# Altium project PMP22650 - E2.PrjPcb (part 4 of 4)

## Sheet PMP22650 CLLLC Primary Sensing.SchDoc
size 431 x 279 mm; Date: Not shown in title block; ApprovedBy: Not shown in title block; CheckedBy: Not shown in title block; Author: Not shown in title block; CompanyName: Not shown in title block; Engineer: Not shown in title block; Organization: Not shown in title block; Address1: Not shown in title block; Address2: Not shown in title block; Address3: Not shown in title block; Address4: Not shown in title block; DocumentNumber: 15; Revision: Use project parameter SCH_Rev; SheetNumber: 15; SheetTotal: 16; PageSetup: Record=PageOptions¦CenterHorizontal=True¦CenterVertical=True¦PrintScale=1.00¦XCorrection=1.00¦YCorrection=1.00¦PrintKind=0¦BorderSize=5000000¦LeftOffset=0¦BottomOffset=0¦Orientation=2¦PaperLength=1000¦PaperWidth=1000¦Scale=100¦PaperSource=15¦PrintQuality=600¦MediaType=1¦DitherType=10¦PaperKind=Letter¦PrintScaleMode=1
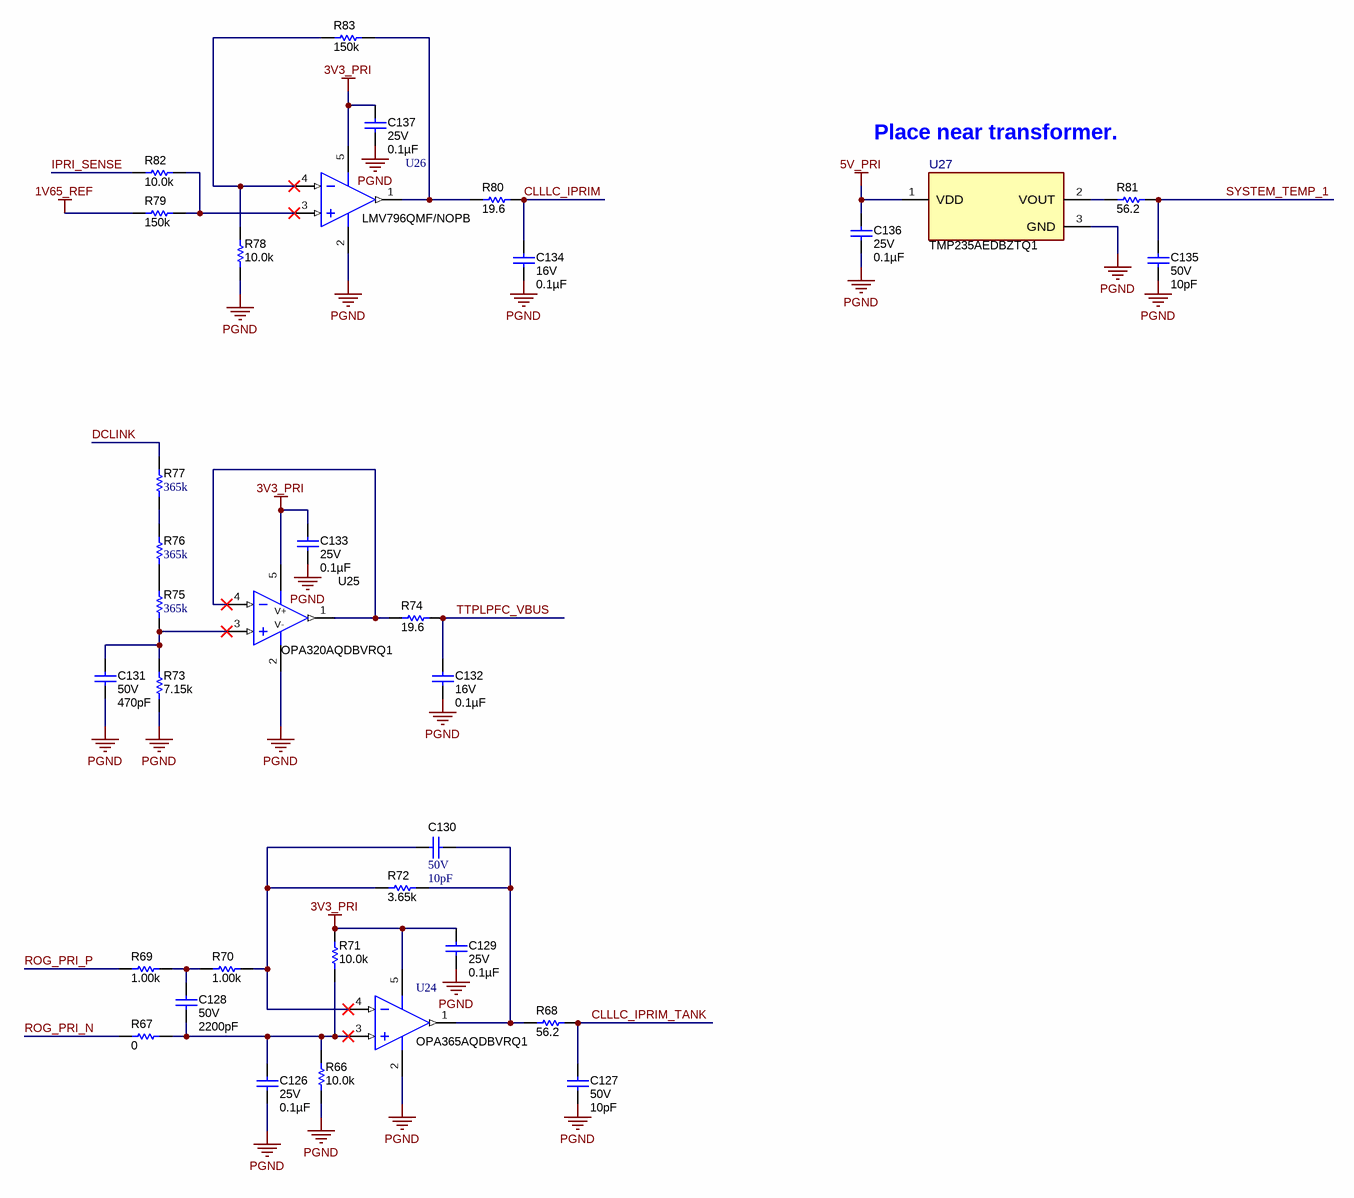
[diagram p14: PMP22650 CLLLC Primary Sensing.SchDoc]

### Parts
C126  VDC_V: 25V  ValueDisplayed: 0.1µF  [0402]  (hidden comment: CGA2B3X7R1E104K050BB)
C127  VDC_V: 50V  ValueDisplayed: 10pF  [0402]  (hidden comment: 04025U100CAT2A)
C128  VDC_V: 50V  ValueDisplayed: 2200pF  [0402]  (hidden comment: CGA2B2X7R1H222K050BA)
C129  VDC_V: 25V  ValueDisplayed: 0.1µF  [0402]  (hidden comment: CGA2B3X7R1E104K050BB)
C130  VDC_V: 50V  ValueDisplayed: 10pF  [0402]  (hidden comment: 04025U100CAT2A)
C131  VDC_V: 50V  ValueDisplayed: 470pF  [0402]  (hidden comment: GCM155R71H471KA37D)
C132  VDC_V: 16V  ValueDisplayed: 0.1µF  [0402]  (hidden comment: GCM155R71C104JA55D)
C133  VDC_V: 25V  ValueDisplayed: 0.1µF  [0402]  (hidden comment: CGA2B3X7R1E104K050BB)
C134  VDC_V: 16V  ValueDisplayed: 0.1µF  [0402]  (hidden comment: GCM155R71C104JA55D)
C135  VDC_V: 50V  ValueDisplayed: 10pF  [0402]  (hidden comment: 04025U100CAT2A)
C136  VDC_V: 25V  ValueDisplayed: 0.1µF  [0402]  (hidden comment: CGA2B3X7R1E104K050BB)
C137  VDC_V: 25V  ValueDisplayed: 0.1µF  [0402]  (hidden comment: CGA2B3X7R1E104K050BB)
R66  ValueDisplayed: 10.0k  [0402]  (hidden comment: ERJPA2F1002X)
R67  ValueDisplayed: 0  [0402]  (hidden comment: CRCW04020000Z0ED)
R68  ValueDisplayed: 56.2  [0402]  (hidden comment: CRCW040256R2FKED)
R69  ValueDisplayed: 1.00k  [0402]  (hidden comment: CRCW04021K00FKED)
R70  ValueDisplayed: 1.00k  [0402]  (hidden comment: CRCW04021K00FKED)
R71  ValueDisplayed: 10.0k  [0402]  (hidden comment: ERJPA2F1002X)
R72  ValueDisplayed: 3.65k  [0402]  (hidden comment: CRCW04023K65FKED)
R73  ValueDisplayed: 7.15k  [0603]  (hidden comment: CRCW06037K15FKEA)
R74  ValueDisplayed: 19.6  [0402]  (hidden comment: CRCW040219R6FKED)
R75  ValueDisplayed: 365k  [1206]  (hidden comment: CRCW1206365KFKEA)
R76  ValueDisplayed: 365k  [1206]  (hidden comment: CRCW1206365KFKEA)
R77  ValueDisplayed: 365k  [1206]  (hidden comment: CRCW1206365KFKEA)
R78  ValueDisplayed: 10.0k  [0402]  (hidden comment: ERJPA2F1002X)
R79  ValueDisplayed: 150k  [0402]  (hidden comment: CRCW0402150KFKED)
R80  ValueDisplayed: 19.6  [0402]  (hidden comment: CRCW040219R6FKED)
R81  ValueDisplayed: 56.2  [0402]  (hidden comment: CRCW040256R2FKED)
R82  ValueDisplayed: 10.0k  [0402]  (hidden comment: ERJPA2F1002X)
R83  ValueDisplayed: 150k  [0402]  (hidden comment: CRCW0402150KFKED)
U24  OPA365AQDBVRQ1  [DBV0005A_N]
U25  OPA320AQDBVRQ1  [DBV0005A_N]
U26  LMV796QMF/NOPB  [DBV0005A_N]
U27  TMP235AEDBZTQ1  [DBZ0003A-MFG]

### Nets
1V65_REF: R79.1
3V3_PRI: C129.1 C133.1 C137.1 R71.2 U24.5(V+) U25.5(V+) U26.5(V+)
5V_PRI: C136.1 U27.1(VDD)
DCLINK: R77.1
PGND: C126.2 C127.2 C129.2 C131.2 C132.2 C133.2 C134.2 C135.2 C136.2 C137.2 R66.1 R73.2 R78.1 U24.2(V-) U25.2(V-) U26.2(V-) U27.3(GND)
CLLLC_IPRIM: C134.1 R80.2
CLLLC_IPRIM_TANK: C127.1 R68.2
IPRI_SENSE: R82.1
ROG_PRI_N: R67.1
ROG_PRI_P: R69.1
SYSTEM_TEMP_1: C135.1 R81.2
TTPLPFC_VBUS: C132.1 R74.2
NetC126_1: C126.1 C128.1 R66.2 R67.2 R71.1 U24.3(IN+)
NetC128_2: C128.2 R69.2 R70.1
NetC130_1: C130.1 R68.1 R72.2 U24.1(VOUT)
NetC130_2: C130.2 R70.2 R72.1 U24.4(IN-)
NetC131_1: C131.1 R73.1 R75.2 U25.3(IN+)
NetR74_1: R74.1 U25.1(OUT) U25.4(IN-)
NetR75_1: R75.1 R76.2
NetR76_1: R76.1 R77.2
NetR78_2: R78.2 R83.1 U26.4(IN-)
NetR79_2: R79.2 R82.2 U26.3(IN+)
NetR80_1: R80.1 R83.2 U26.1(OUT)
NetR81_1: R81.1 U27.2(VOUT)

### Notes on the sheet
- Place near transformer.

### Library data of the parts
C126 C129 C133 C136 C137 = CMP-0080610-1: CAP, CERM, 0.1 µF, 25 V,+/- 10%, X7R, AEC-Q200 Grade 1, 0402; Manufacturer: TDK; TaMin_C: -55°C; Polarized: N; SizeAreaWB_mm2: 3; U/M: EA; Value: 0.1uF; TaMax_C: 125°C; SizeZ_mm: 0.6; SizeX_mm: 1; SizeY_mm: 0.5; AEC Qualified: Y; Cap_F: 100nF; AEC Category: Q200
C127 C130 C135 = CMP-0064911-2: CAP, CERM, 10 pF, 50 V,+/- 2.5%, C0G/NP0, AEC-Q200 Grade 1, 0402; Manufacturer: AVX; TaMin_C: -55°C; Polarized: N; SizeAreaWB_mm2: 3; Value1: Unknown; U/M: EA; Value: 10pF; TaMax_C: 125°C; SizeZ_mm: 0.6; SizeX_mm: 1; SizeY_mm: 0.5; AEC Qualified: Y; AEC Category: Q200
C128 = CMP-0006317-2: CAP, CERM, 2200 pF, 50 V, +/- 10%, X7R, AEC-Q200 Grade 1, 0402; Manufacturer: TDK; TaMin_C: -55°C; ESR_ohm: 1.07794; Polarized: N; SizeAreaWB_mm2: 3; Value1: 1.07794 ohm; U/M: EA; Value: 2200pF; TaMax_C: 125°C; SizeZ_mm: 0.6; SizeX_mm: 1; SizeY_mm: 0.5; AEC Qualified: Y; Cap_F: 2.2nF; IRMS_A: 264.071mA; AEC Category: Q200
C131 = CMP-0006360-2: CAP, CERM, 470 pF, 50 V, +/- 10%, X7R, AEC-Q200 Grade 1, 0402; Manufacturer: MuRata; TaMin_C: -55°C; Polarized: N; SizeAreaWB_mm2: 3; Value1: Unknown; U/M: EA; Value: 470pF; TaMax_C: 125°C; SizeZ_mm: 0.6; SizeX_mm: 1; SizeY_mm: 0.5; AEC Qualified: Y; AEC Category: Q200
C132 C134 = CMP-0080702-1: CAP, CERM, 0.1 µF, 16 V,+/- 5%, X7R, AEC-Q200 Grade 1, 0402; Manufacturer: MuRata; Cap_F: 100nF; SizeAreaWB_mm2: 3; SizeArea_mm2: 0.5; AEC Qualified: Y; AEC Category: Q200; Value: 0.1uF; TaMax_C: 125°C; SizeZ_mm: 0.6; AEC Grade: 1; Polarized: N; TaMin_C: -55°C; U/M: EA
R66 R71 R78 R82 = CMP-0078779-1: RES, 10.0 k, 1%, 0.2 W, AEC-Q200 Grade 0, 0402; Manufacturer: Panasonic; Value_Code: 10k0; SizeArea_mm2: 0.5; AEC Qualified: Y; AEC Category: Q200; Res_ohm: 10k; Value: 10.0k; SizeZ_mm: 0.6; EIA_Code: E96; TempCo: 100 ppm/C; AEC Grade: 0; Power_W: 200mW; VDC_V: 50V; Value2: 0.2W; SizeX_mm: 1
R67 = CMP-0026822-3: RES, 0, 5%, 0.063 W, AEC-Q200 Grade 0, 0402; Manufacturer: Vishay-Dale; Power_W: 63mW; TempCo: 200 ppm/C; Value_Code: 0000; Value: 0; EIA_Code: E24; SizeX_mm: 1; SizeY_mm: 0.5; SizeZ_mm: 0.6; Value2: 0.063W; AEC Qualified: Y; VDC_V: 50V; AEC Category: Q200
R68 R81 = CMP-0026454-2: RES, 56.2, 1%, 0.063 W, AEC-Q200 Grade 0, 0402; Manufacturer: Vishay-Dale; Power_W: 63mW; TempCo: 100 ppm/C; Value_Code: 56R2; Value: 56.2; EIA_Code: E96; SizeX_mm: 1; SizeY_mm: 0.5; SizeZ_mm: 0.6; Value2: 0.063W; AEC Qualified: Y; VDC_V: 50V; AEC Category: Q200; AEC Grade: 0
R69 R70 = CMP-0026071-3: RES, 1.00 k, 1%, 0.063 W, AEC-Q200 Grade 0, 0402; Manufacturer: Vishay-Dale; Power_W: 63mW; TempCo: 100 ppm/C; Value_Code: 1k00; Value: 1.00k; EIA_Code: E96; Res_ohm: 1k; SizeX_mm: 1; SizeY_mm: 0.5; SizeZ_mm: 0.6; Value2: 0.063W; AEC Qualified: Y; VDC_V: 50V; AEC Category: Q200; AEC Grade: 0
R72 = CMP-0026337-2: RES, 3.65 k, 1%, 0.063 W, AEC-Q200 Grade 0, 0402; Manufacturer: Vishay-Dale; Power_W: 63mW; TempCo: 100 ppm/C; Value_Code: 3k65; Value: 3.65k; EIA_Code: E96; SizeX_mm: 1; SizeY_mm: 0.5; SizeZ_mm: 0.6; Value2: 0.063W; AEC Qualified: Y; VDC_V: 50V; AEC Category: Q200; AEC Grade: 0
R73 = CMP-0022599-4: RES, 7.15 k, 1%, 0.1 W, AEC-Q200 Grade 0, 0603; Manufacturer: Vishay-Dale; Power_W: 100mW; TempCo: 100 ppm/C; Value_Code: 7k15; Value: 7.15k; EIA_Code: E96; SizeX_mm: 1.6; SizeY_mm: 0.8; SizeZ_mm: 1; Value2: 0.1W; SizeArea_mm2: 1.28; AEC Qualified: Y; VDC_V: 75V; AEC Category: Q200; AEC Grade: 0
R74 R80 = CMP-0026070-3: RES, 19.6, 1%, 0.063 W, AEC-Q200 Grade 0, 0402; Manufacturer: Vishay-Dale; Power_W: 63mW; TempCo: 100 ppm/C; Value_Code: 19R6; Value: 19.6; EIA_Code: E96; SizeX_mm: 1; SizeY_mm: 0.5; SizeZ_mm: 0.6; Value2: 0.063W; AEC Qualified: Y; VDC_V: 50V; AEC Category: Q200; AEC Grade: 0
R75-R77 = CMP-0016927-3: RES, 365 k, 1%, 0.25 W, AEC-Q200 Grade 0, 1206; Manufacturer: Vishay-Dale; Power_W: 250mW; TempCo: 100 ppm/C; Value: 365k; EIA_Code: E96; SizeX_mm: 3.2; SizeY_mm: 1.6; SizeZ_mm: 1.35; Value2: 0.25W; SizeArea_mm2: 5.12; AEC Qualified: Y; VDC_V: 200V; AEC Category: Q200; AEC Grade: 0
R79 R83 = CMP-0026021-3: RES, 150 k, 1%, 0.063 W, AEC-Q200 Grade 0, 0402; Manufacturer: Vishay-Dale; Power_W: 63mW; TempCo: 100 ppm/C; Value: 150k; EIA_Code: E96; SizeX_mm: 1; SizeY_mm: 0.5; SizeZ_mm: 0.6; Value2: 0.063W; AEC Qualified: Y; VDC_V: 50V; AEC Category: Q200; AEC Grade: 0
U24 = CMP-0041005-2: Automotive Catalog, 50 MHz, Low-Noise, Single-Supply Rail-to-Rail Operational Amplifier, 2.2 to 5.5 V, -40 to 125 degC, 5-pin SOT23 (DBV5), Green (RoHS & no Sb/Br); Manufacturer: Texas Instruments; Sub Family: High Speed Amplifier (>=50MHz), Low Input Bias Current Amp (<=10pA), Low Offset Voltage Amplifier (<=500uV), Low Supply Voltage Amplifier (<=2.7V); Total Supply Voltage(Min)(+5V is 5, +/-5V is 10): 2.2; Slew Rate(Typ)(V/us): 25; Vio (25C)(Max)(mV): 0.2; Total Supply Voltage(Max)(+5V is 5, +/-5V is 10): 5.5; IIB(Max)(pA): 10; Offset Drift(Typ)(uV/C): 1; Iq per channel(Max)(mA): 5; CMRR(Min)(dB): 100
U25 = CMP-0077859-1: Automotive Qualified Precision, Zero-Crossover, 20MHz, 0.9pA Ib, RRIO, CMOS Operational Amplifier, DBV0005A (SOT-23-5); Alternate PartNumber: OPA320AQDBVTQ1; Alternate Manufacturer: Texas Instruments; SizeAreaWB_mm2: 14.82; SizeZ_mm: 1.45; SizeX_mm: 2.8; SizeY_mm: 2.9; SizeArea_mm2: 8.12; CompType: IC; AEC Qualified: Y; AEC Category: Q200
U26 = CMP-0068826-2: 17 MHz, Low Noise, CMOS Input, 1.8V Operational Amplifiers, DBV0005A (SOT-23-5); Manufacturer: Texas Instruments; CompType: IC; AEC Category: Q200; AEC Qualified: Y; Rating: Automotive; SizeAreaWB_mm2: 14.82; SizeArea_mm2: 8.12; SizeX_mm: 2.8; SizeY_mm: 2.9; SizeZ_mm: 1.45
U27 = CMP-0090472-1: Temperature Sensor Analog, Local -40°C ~ 150°C 10mV/°C SOT-23-3; Manufacturer: Texas Instruments; TJmax_C: +150°C; Min Supply Voltage: 2.3V; SizeZ_mm: 1.12mm; Max Supply Voltage: 5.5V; Interface: Other; AEC Qualified: Yes; Output Voltage: 500mV; AEC Grade: Grade 0; Standoff Height: 0.01mm; Sensor Output: Analog Voltage; Operating Supply Current: 9uA

## Sheet PMP22650 CLLLC Secondary Sensing.SchDoc
size 431 x 279 mm; Date: Not shown in title block; ApprovedBy: Not shown in title block; CheckedBy: Not shown in title block; Author: Not shown in title block; CompanyName: Not shown in title block; Engineer: Not shown in title block; Organization: Not shown in title block; Address1: Not shown in title block; Address2: Not shown in title block; Address3: Not shown in title block; Address4: Not shown in title block; DocumentNumber: 16; Revision: Use project parameter SCH_Rev; SheetNumber: 16; SheetTotal: 16; PageSetup: Record=PageOptions¦CenterHorizontal=True¦CenterVertical=True¦PrintScale=1.00¦XCorrection=1.00¦YCorrection=1.00¦PrintKind=0¦BorderSize=5000000¦LeftOffset=0¦BottomOffset=0¦Orientation=2¦PaperLength=1000¦PaperWidth=1000¦Scale=100¦PaperSource=15¦PrintQuality=600¦MediaType=1¦DitherType=10¦PaperKind=Letter¦PrintScaleMode=1
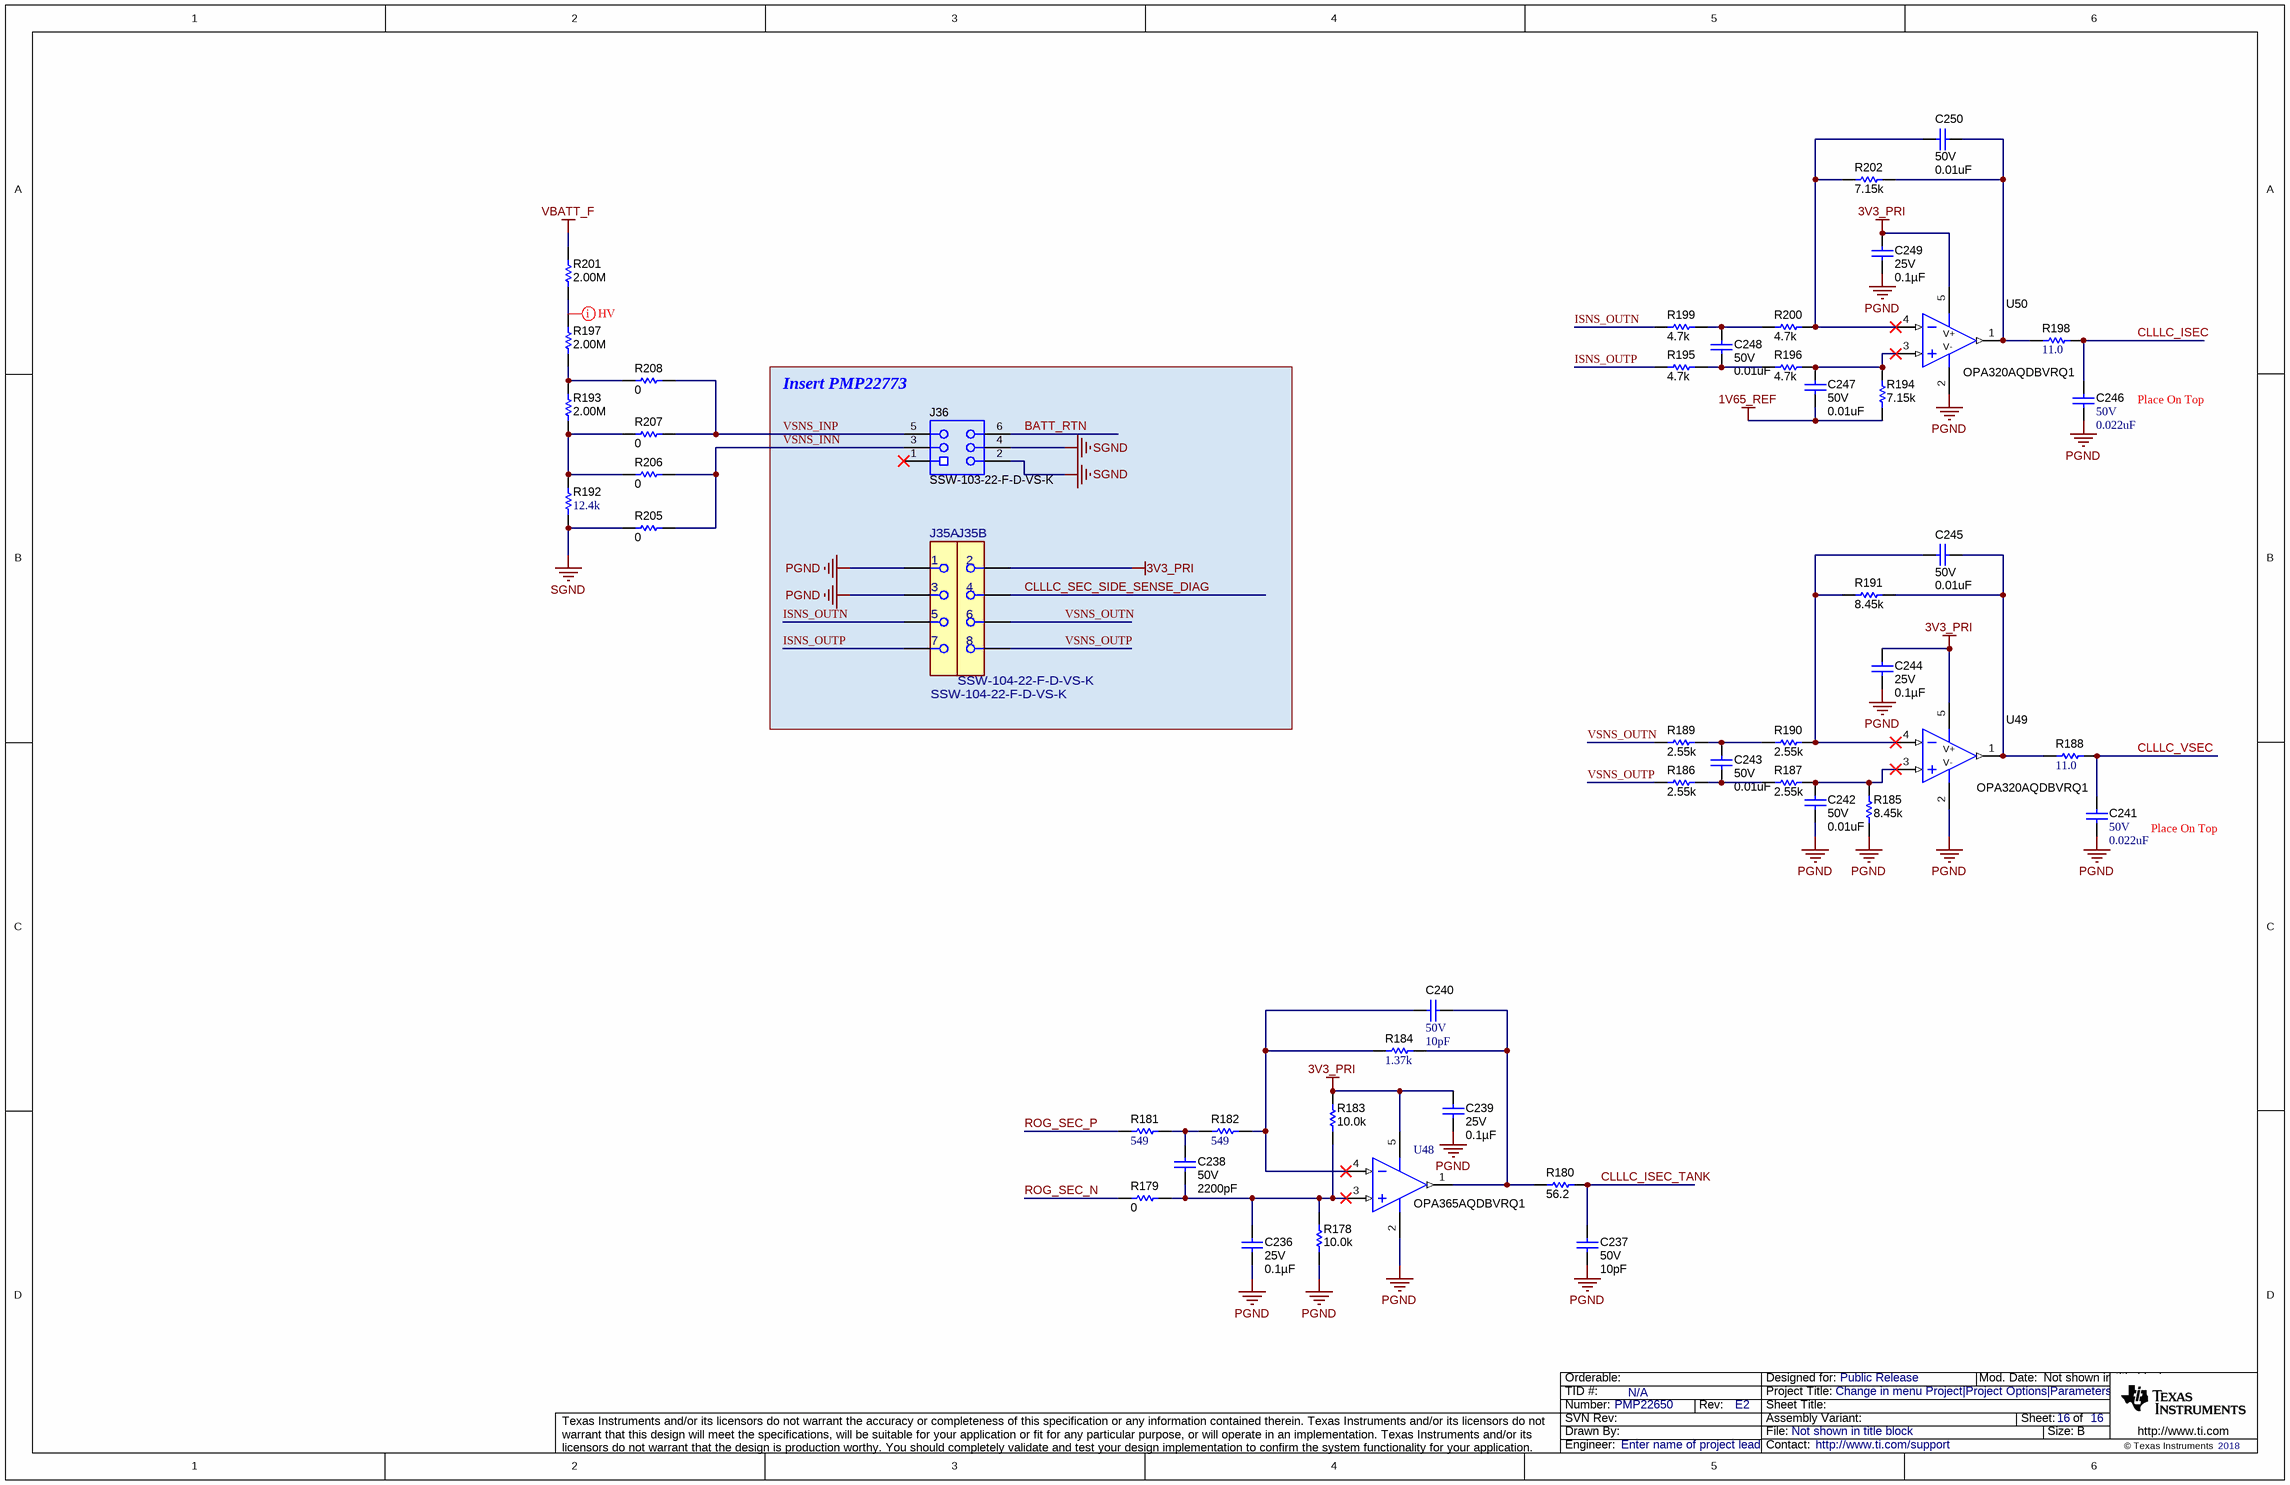
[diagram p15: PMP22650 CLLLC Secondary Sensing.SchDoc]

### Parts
C236  VDC_V: 25V  ValueDisplayed: 0.1µF  [0402]  (hidden comment: CGA2B3X7R1E104K050BB)
C237  VDC_V: 50V  ValueDisplayed: 10pF  [0402]  (hidden comment: 04025U100CAT2A)
C238  VDC_V: 50V  ValueDisplayed: 2200pF  [0402]  (hidden comment: CGA2B2X7R1H222K050BA)
C239  VDC_V: 25V  ValueDisplayed: 0.1µF  [0402]  (hidden comment: CGA2B3X7R1E104K050BB)
C240  VDC_V: 50V  ValueDisplayed: 10pF  [0402]  (hidden comment: 04025U100CAT2A)
C241  VDC_V: 50V  ValueDisplayed: 0.022uF  [0402]  (hidden comment: CGA2B3X7R1H223K050BB)
C242  VDC_V: 50V  ValueDisplayed: 0.01uF  [0402]  (hidden comment: CGA2B3X7R1H103K050BB)
C243  VDC_V: 50V  ValueDisplayed: 0.01uF  [0402]  (hidden comment: CGA2B3X7R1H103K050BB)
C244  VDC_V: 25V  ValueDisplayed: 0.1µF  [0402]  (hidden comment: CGA2B3X7R1E104K050BB)
C245  VDC_V: 50V  ValueDisplayed: 0.01uF  [0402]  (hidden comment: CGA2B3X7R1H103K050BB)
C246  VDC_V: 50V  ValueDisplayed: 0.022uF  [0402]  (hidden comment: CGA2B3X7R1H223K050BB)
C247  VDC_V: 50V  ValueDisplayed: 0.01uF  [0402]  (hidden comment: CGA2B3X7R1H103K050BB)
C248  VDC_V: 50V  ValueDisplayed: 0.01uF  [0402]  (hidden comment: CGA2B3X7R1H103K050BB)
C249  VDC_V: 25V  ValueDisplayed: 0.1µF  [0402]  (hidden comment: CGA2B3X7R1E104K050BB)
C250  VDC_V: 50V  ValueDisplayed: 0.01uF  [0402]  (hidden comment: CGA2B3X7R1H103K050BB)
J35  SSW-104-22-F-D-VS-K  [FP-SSW-104-22-F-D-VS-K_HDR8-MFG]  (parts A,B of 2)
J36  SSW-103-22-F-D-VS-K  [SAMTEC_SSW-103-22-F-D-VS-K]
R178  ValueDisplayed: 10.0k  [0402]  (hidden comment: ERJPA2F1002X)
R179  ValueDisplayed: 0  [0402]  (hidden comment: CRCW04020000Z0ED)
R180  ValueDisplayed: 56.2  [0402]  (hidden comment: CRCW040256R2FKED)
R181  ValueDisplayed: 549  [0402]  (hidden comment: CRCW0402549RFKED)
R182  ValueDisplayed: 549  [0402]  (hidden comment: CRCW0402549RFKED)
R183  ValueDisplayed: 10.0k  [0402]  (hidden comment: ERJPA2F1002X)
R184  ValueDisplayed: 1.37k  [0402]  (hidden comment: CRCW04021K37FKED)
R185  ValueDisplayed: 8.45k  [0603]  (hidden comment: CRCW06038K45FKEA)
R186  ValueDisplayed: 2.55k  [0402]  (hidden comment: CRCW04022K55FKED)
R187  ValueDisplayed: 2.55k  [0402]  (hidden comment: CRCW04022K55FKED)
R188  ValueDisplayed: 11.0  [0402]  (hidden comment: CRCW040211R0FKED)
R189  ValueDisplayed: 2.55k  [0402]  (hidden comment: CRCW04022K55FKED)
R190  ValueDisplayed: 2.55k  [0402]  (hidden comment: CRCW04022K55FKED)
R191  ValueDisplayed: 8.45k  [0603]  (hidden comment: CRCW06038K45FKEA)
R192  ValueDisplayed: 12.4k  [1206]  (hidden comment: ERJ-8ENF1242V)
R193  ValueDisplayed: 2.00M  [1206]  (hidden comment: CRCW12062M00FKEA)
R194  ValueDisplayed: 7.15k  [0402]  (hidden comment: CRCW04027K15FKED)
R195  ValueDisplayed: 4.7k  [0402]  (hidden comment: CRCW04024K70JNED)
R196  ValueDisplayed: 4.7k  [0402]  (hidden comment: CRCW04024K70JNED)
R197  ValueDisplayed: 2.00M  [1206]  (hidden comment: CRCW12062M00FKEA)
R198  ValueDisplayed: 11.0  [0402]  (hidden comment: CRCW040211R0FKED)
R199  ValueDisplayed: 4.7k  [0402]  (hidden comment: CRCW04024K70JNED)
R200  ValueDisplayed: 4.7k  [0402]  (hidden comment: CRCW04024K70JNED)
R201  ValueDisplayed: 2.00M  [1206]  (hidden comment: CRCW12062M00FKEA)
R202  ValueDisplayed: 7.15k  [0402]  (hidden comment: CRCW04027K15FKED)
R205  ValueDisplayed: 0  [0402]  (hidden comment: CRCW04020000Z0ED)
R206  ValueDisplayed: 0  [0402]  (hidden comment: CRCW04020000Z0ED)
R207  ValueDisplayed: 0  [0402]  (hidden comment: CRCW04020000Z0ED)
R208  ValueDisplayed: 0  [0402]  (hidden comment: CRCW04020000Z0ED)
U48  OPA365AQDBVRQ1  [DBV0005A_N]
U49  OPA320AQDBVRQ1  [DBV0005A_N]
U50  OPA320AQDBVRQ1  [DBV0005A_N]

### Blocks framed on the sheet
Insert PMP22773: J35 J36

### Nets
1V65_REF: C247.1 R194.1
3V3_PRI: C239.1 C244.1 C249.1 J35.2 R183.2 U48.5(V+) U49.5(V+) U50.5(V+)
PGND: C236.2 C237.2 C239.2 C241.2 C242.1 C244.2 C246.2 C249.2 J35.1 J35.3 R178.1 R185.1 U48.2(V-) U49.2(V-) U50.2(V-)
SGND: J36.2 J36.4 R192.2 R205.1
VBATT_F: R201.2
BATT_RTN: J36.6
CLLLC_ISEC: C246.1 R198.2
CLLLC_ISEC_TANK: C237.1 R180.2
CLLLC_SEC_SIDE_SENSE_DIAG: J35.4
CLLLC_VSEC: C241.1 R188.2
ISNS_OUTN: J35.5 R199.1
ISNS_OUTP: J35.7 R195.1
ROG_SEC_N: R179.1
ROG_SEC_P: R181.1
VSNS_INN: J36.3 R205.2 R206.2
VSNS_INP: J36.5 R207.2 R208.2
VSNS_OUTN: J35.6 R189.1
VSNS_OUTP: J35.8 R186.1
NetC236_1: C236.1 C238.1 R178.2 R179.2 R183.1 U48.3(IN+)
NetC238_2: C238.2 R181.2 R182.1
NetC240_1: C240.1 R180.1 R184.2 U48.1(VOUT)
NetC240_2: C240.2 R182.2 R184.1 U48.4(IN-)
NetC242_2: C242.2 R185.2 R187.2 U49.3(IN+)
NetC243_1: C243.1 R186.2 R187.1
NetC243_2: C243.2 R189.2 R190.1
NetC245_1: C245.1 R188.1 R191.2 U49.1(OUT)
NetC245_2: C245.2 R190.2 R191.1 U49.4(IN-)
NetC247_2: C247.2 R194.2 R196.2 U50.3(IN+)
NetC248_1: C248.1 R195.2 R196.1
NetC248_2: C248.2 R199.2 R200.1
NetC250_1: C250.1 R198.1 R202.2 U50.1(OUT)
NetC250_2: C250.2 R200.2 R202.1 U50.4(IN-)
NetR192_1: R192.1 R193.1 R206.1 R207.1
NetR193_2: R193.2 R197.1 R208.1
NetR197_2: R197.2 R201.1

Not connected (* = marked no-connect by the designer): J36 1*

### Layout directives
mark named HV: NetR197_2

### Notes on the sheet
- Place On Top

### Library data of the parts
C236 C239 C244 C249 = CMP-0080610-1: as C126 on sheet PMP22650 CLLLC Primary Sensing
C237 C240 = CMP-0064911-2: as C127 on sheet PMP22650 CLLLC Primary Sensing
C238 = CMP-0006317-2: as C128 on sheet PMP22650 CLLLC Primary Sensing
C241 C246 = CMP-0006328-2: CAP, CERM, 0.022 uF, 50 V, +/- 10%, X7R, AEC-Q200 Grade 1, 0402; Manufacturer: TDK; TaMin_C: -55°C; Polarized: N; SizeAreaWB_mm2: 3; Value1: 0.141987 ohm; U/M: EA; TaMax_C: 125°C; SizeZ_mm: 0.6; SizeX_mm: 1; SizeY_mm: 0.5; AEC Qualified: Y; Cap_F: 22nF; AEC Category: Q200; ESR_ohm: 0.142; IRMS_A: 451.393mA
C242 C243 C245 C247 C248 C250 = CMP-0006324-2: CAP, CERM, 0.01 uF, 50 V, +/- 10%, X7R, AEC-Q200 Grade 1, 0402; Manufacturer: TDK; TaMin_C: -55°C; ESR_ohm: 0.333065; Polarized: N; SizeAreaWB_mm2: 3; Value1: 0.333065 ohm; U/M: EA; Value: 0.01uF; TaMax_C: 125°C; SizeZ_mm: 0.6; SizeX_mm: 1; SizeY_mm: 0.5; AEC Qualified: Y; Cap_F: 10nF; IRMS_A: 323.373mA; AEC Category: Q200
J35 = CMP-0090885-1: 8 Position Receptacle Connector  Surface Mount; Manufacturer: Samtec; Standoff Height: 0.97mm; Is Female: yes; Row_Count: 2; ContactFinish: Gold,Nickel; Voltage_V: 655V; AEC Qualified: No; Current_A: 4.7A; Conn Gender: Female; SizeZ_mm: 10.21mm; Conn Orientation: Vertical; DUT-Pitch_mm: 2.54mm
J36 = CMP-0055666-1: Receptacle, 2.54mm, 3x2, Tin, SMT; Manufacturer: Samtec; CNHeader: FALSE; Current_A: 5.7A; Gender: Female; CompType: Socket Strip; Row_Count: 2; RowSpacing_mm: 2.54; ContactFinish: Gold; CT: TRUE; Cert_UL: Y
R178 R183 = CMP-0078779-1: as R66 on sheet PMP22650 CLLLC Primary Sensing
R179 R205-R208 = CMP-0026822-3: as R67 on sheet PMP22650 CLLLC Primary Sensing
R180 = CMP-0026454-2: as R68 on sheet PMP22650 CLLLC Primary Sensing
R181 R182 = CMP-0026448-2: RES, 549, 1%, 0.063 W, AEC-Q200 Grade 0, 0402; Manufacturer: Vishay-Dale; Power_W: 63mW; TempCo: 100 ppm/C; Value_Code: 549R; Value: 549; EIA_Code: E96; SizeX_mm: 1; SizeY_mm: 0.5; SizeZ_mm: 0.6; Value2: 0.063W; AEC Qualified: Y; VDC_V: 50V; AEC Category: Q200; AEC Grade: 0
R184 = CMP-0026084-3: RES, 1.37 k, 1%, 0.063 W, AEC-Q200 Grade 0, 0402; Manufacturer: Vishay-Dale; Power_W: 63mW; TempCo: 100 ppm/C; Value_Code: 1k37; Value: 1.37k; EIA_Code: E96; SizeX_mm: 1; SizeY_mm: 0.5; SizeZ_mm: 0.6; Value2: 0.063W; AEC Qualified: Y; VDC_V: 50V; AEC Category: Q200; AEC Grade: 0
R185 R191 = CMP-0022636-4: RES, 8.45 k, 1%, 0.1 W, AEC-Q200 Grade 0, 0603; Manufacturer: Vishay-Dale; Power_W: 100mW; TempCo: 100 ppm/C; Value_Code: 8k45; Value: 8.45k; EIA_Code: E96; SizeX_mm: 1.6; SizeY_mm: 0.8; SizeZ_mm: 1; Value2: 0.1W; SizeArea_mm2: 1.28; AEC Qualified: Y; VDC_V: 75V; AEC Category: Q200; AEC Grade: 0
R186 R187 R189 R190 = CMP-0026238-2: RES, 2.55 k, 1%, 0.063 W, AEC-Q200 Grade 0, 0402; Manufacturer: Vishay-Dale; Power_W: 63mW; TempCo: 100 ppm/C; Value_Code: 2k55; Value: 2.55k; EIA_Code: E96; SizeX_mm: 1; SizeY_mm: 0.5; SizeZ_mm: 0.6; Value2: 0.063W; AEC Qualified: Y; VDC_V: 50V; AEC Category: Q200; AEC Grade: 0
R188 R198 = CMP-0025979-3: RES, 11.0, 1%, 0.063 W, AEC-Q200 Grade 0, 0402; Manufacturer: Vishay-Dale; Power_W: 63mW; TempCo: 100 ppm/C; Value_Code: 11R0; Value: 11.0; EIA_Code: E96; Res_ohm: 11; SizeX_mm: 1; SizeY_mm: 0.5; SizeZ_mm: 0.6; Value2: 0.063W; AEC Qualified: Y; VDC_V: 50V; AEC Category: Q200; AEC Grade: 0
R192 = CMP-0017331-3: RES, 12.4 k, 1%, 0.25 W, AEC-Q200 Grade 0, 1206; Manufacturer: Panasonic; Power_W: 250mW; TempCo: 100 ppm/C; Value_Code: 12k4; Value: 12.4k; EIA_Code: E96; SizeX_mm: 3.2; SizeY_mm: 1.6; SizeZ_mm: 1.35; Value2: 0.25W; SizeArea_mm2: 5.12; AEC Qualified: Y; VDC_V: 200V; AEC Category: Q200; AEC Grade: 0; SizeAreaWB_mm2: 10.92
R193 R197 R201 = CMP-0016861-3: RES, 2.00 M, 1%, 0.25 W, AEC-Q200 Grade 0, 1206; Manufacturer: Vishay-Dale; Power_W: 250mW; TempCo: 100 ppm/C; Value_Code: 2M00; Value: 2.00Meg; EIA_Code: E96; Res_ohm: 2M; SizeX_mm: 3.2; SizeY_mm: 1.6; SizeZ_mm: 1.35; Value2: 0.25W; SizeArea_mm2: 5.12; AEC Qualified: Y; VDC_V: 200V; AEC Category: Q200; AEC Grade: 0
R194 R202 = CMP-0026553-2: RES, 7.15 k, 1%, 0.063 W, AEC-Q200 Grade 0, 0402; Manufacturer: Vishay-Dale; Power_W: 63mW; TempCo: 100 ppm/C; Value_Code: 7k15; Value: 7.15k; EIA_Code: E96; SizeX_mm: 1; SizeY_mm: 0.5; SizeZ_mm: 0.6; Value2: 0.063W; AEC Qualified: Y; VDC_V: 50V; AEC Category: Q200; AEC Grade: 0
R195 R196 R199 R200 = CMP-0026938-5: RES, 4.7 k, 5%, 0.063 W, AEC-Q200 Grade 0, 0402; Manufacturer: Vishay-Dale; Power_W: 63mW; TempCo: 200 ppm/C; Value_Code: 4k70; Value: 4.7k; EIA_Code: E24; SizeX_mm: 1; SizeY_mm: 0.5; SizeZ_mm: 0.6; Value2: 0.063W; AEC Qualified: Y; VDC_V: 50V; AEC Category: Q200; AEC Grade: 0
U48 = CMP-0041005-2: as U24 on sheet PMP22650 CLLLC Primary Sensing
U49 U50 = CMP-0077859-1: as U25 on sheet PMP22650 CLLLC Primary Sensing

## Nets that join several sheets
1V65_REF: PMP22650 PFC Power Stage (5 pins), PMP22650 Control (J26.26), PMP22650 Bias Power and Monitors (C23.1 R7.2), PMP22650 CLLLC Primary Sensing (R79.1), PMP22650 CLLLC Secondary Sensing (C247.1 R194.1)
3V3_PRI: PMP22650 PFC Power Stage (14 pins), PMP22650 PFC GaN PH1 (6 pins), PMP22650 PFC GaN PH2 (6 pins), PMP22650 PFC LF FET Gate Driver (C198.1 U42.3 U42.8), PMP22650 Control (16 pins), PMP22650 Bias Power and Monitors (14 pins), PMP22650 CLLLC GaN Phase A (6 pins), PMP22650 CLLLC GaN Phase B (6 pins), PMP22650 CLLLC GaN Phase C (6 pins), PMP22650 CLLLC GaN Phase D (6 pins), PMP22650 CLLLC Primary Sensing (7 pins), PMP22650 CLLLC Secondary Sensing (8 pins)
5V_PRI: PMP22650 PFC GaN PH1 (J27.5), PMP22650 PFC GaN PH2 (J29.5), PMP22650 PFC LF FET Gate Driver (J31.5), PMP22650 Control (6 pins), PMP22650 Bias Power and Monitors (16 pins), PMP22650 CLLLC Power Stage (J12.5), PMP22650 CLLLC GaN Phase A (J16.5), PMP22650 CLLLC GaN Phase B (J18.5), PMP22650 CLLLC GaN Phase C (J20.5), PMP22650 CLLLC GaN Phase D (J22.5), PMP22650 CLLLC Primary Sensing (C136.1 U27.1)
12V_PRI: PMP22650 PFC Power Stage (C214.1 R157.2 R158.2), PMP22650 Bias Power and Monitors (6 pins), PMP22650 CLLLC Power Stage (J12.1 J12.2)
12V_SW: PMP22650 Active EMI (J34.1), PMP22650 PFC GaN PH1 (J27.1 J27.3), PMP22650 PFC GaN PH2 (J29.1 J29.3), PMP22650 PFC LF FET Gate Driver (J31.1 J31.3), PMP22650 Bias Power and Monitors (Q4.1 Q4.2 Q4.5 Q4.6), PMP22650 CLLLC GaN Phase A (J16.1 J16.3), PMP22650 CLLLC GaN Phase B (J18.1 J18.3), PMP22650 CLLLC GaN Phase C (J20.1 J20.3), PMP22650 CLLLC GaN Phase D (J22.1 J22.3)
DCLINK: PMP22650 PFC Power Stage (13 pins), PMP22650 PFC GaN PH1 (24 pins), PMP22650 PFC GaN PH2 (24 pins), PMP22650 Control (R96.1), PMP22650 CLLLC Power Stage (10 pins), PMP22650 CLLLC GaN Phase A (24 pins), PMP22650 CLLLC GaN Phase B (24 pins), PMP22650 CLLLC Primary Sensing (R77.1)
EARTH: PMP22650 Active EMI (C234.1 C235.2), PMP22650 PFC Power Stage (9 pins)
PGND: PMP22650 Active EMI (6 pins), PMP22650 PFC Power Stage (38 pins), PMP22650 PFC GaN PH1 (13 pins), PMP22650 PFC GaN PH2 (13 pins), PMP22650 PFC LF FET Gate Driver (9 pins), PMP22650 Control (35 pins), PMP22650 Bias Power and Monitors (39 pins), PMP22650 CLLLC Power Stage (14 pins), PMP22650 CLLLC GaN Phase A (54 pins), PMP22650 CLLLC GaN Phase B (54 pins), PMP22650 CLLLC GaN Phase C (13 pins), PMP22650 CLLLC GaN Phase D (13 pins), PMP22650 CLLLC Primary Sensing (17 pins), PMP22650 CLLLC Secondary Sensing (15 pins)
SGND: PMP22650 CLLLC Power Stage (12 pins), PMP22650 CLLLC GaN Phase C (41 pins), PMP22650 CLLLC GaN Phase D (41 pins), PMP22650 CLLLC Secondary Sensing (J36.2 J36.4 R192.2 R205.1)
VBATT_F: PMP22650 CLLLC Power Stage (6 pins), PMP22650 CLLLC GaN Phase C (24 pins), PMP22650 CLLLC GaN Phase D (24 pins), PMP22650 CLLLC Secondary Sensing (R201.2)
VDD: PMP22650 Control (J26.118), PMP22650 Bias Power and Monitors (U4.10)
VDDIO: PMP22650 Control (J26.119), PMP22650 Bias Power and Monitors (U5.1)
AC_N: PMP22650 PFC Power Stage (10 pins), PMP22650 PFC LF FET Gate Driver (7 pins)
ACTIVE_EMI_INJ_PD_LEVEL: PMP22650 Active EMI (J34.8), PMP22650 Control (J26.9)
ACTIVE_EMI_INJ_PD_PULSE: PMP22650 Active EMI (J34.7), PMP22650 Control (J26.69)
ACTIVE_EMI_INJ_PU_PULSE: PMP22650 Active EMI (J34.6), PMP22650 Control (J26.67)
ACTIVE_EMI_RESET: PMP22650 Active EMI (R176.2), PMP22650 Control (J26.87)
ACTIVE_EMI_SENSE: PMP22650 Active EMI (C233.1 Q10.3 R177.1), PMP22650 Control (J26.36)
BATT_RTN: PMP22650 CLLLC Power Stage (9 pins), PMP22650 CLLLC Secondary Sensing (J36.6)
CLLLC_GAN_OC_PRIM_LEG1_H: PMP22650 Control (J26.99), PMP22650 CLLLC GaN Phase A (U10.13)
CLLLC_GAN_OC_PRIM_LEG1_L: PMP22650 Control (J26.107), PMP22650 CLLLC GaN Phase A (U8.13)
CLLLC_GAN_OC_PRIM_LEG2_H: PMP22650 Control (J26.109), PMP22650 CLLLC GaN Phase B (U14.13)
CLLLC_GAN_OC_PRIM_LEG2_L: PMP22650 Control (J26.100), PMP22650 CLLLC GaN Phase B (U12.13)
CLLLC_GAN_OC_SEC_LEG1_H: PMP22650 Control (J26.104), PMP22650 CLLLC GaN Phase C (U18.13)
CLLLC_GAN_OC_SEC_LEG1_L: PMP22650 Control (J26.106), PMP22650 CLLLC GaN Phase C (U16.13)
CLLLC_GAN_OC_SEC_LEG2_H: PMP22650 Control (J26.108), PMP22650 CLLLC GaN Phase D (U22.13)
CLLLC_GAN_OC_SEC_LEG2_L: PMP22650 Control (J26.110), PMP22650 CLLLC GaN Phase D (U20.13)
CLLLC_IPRIM: PMP22650 Control (J26.34), PMP22650 CLLLC Primary Sensing (C134.1 R80.2)
CLLLC_IPRIM_TANK: PMP22650 Control (J26.33 J26.37), PMP22650 CLLLC Primary Sensing (C127.1 R68.2)
CLLLC_ISEC: PMP22650 Control (J26.21), PMP22650 CLLLC Secondary Sensing (C246.1 R198.2)
CLLLC_ISEC_TANK: PMP22650 Control (J26.28), PMP22650 CLLLC Secondary Sensing (C237.1 R180.2)
CLLLC_LC_CHANGE: PMP22650 Control (J26.62), PMP22650 CLLLC Power Stage (J12.6)
CLLLC_PRIM_FAULT_LEG1_H: PMP22650 Control (U31.1), PMP22650 CLLLC GaN Phase A (U10.12)
CLLLC_PRIM_FAULT_LEG1_L: PMP22650 Control (U31.2), PMP22650 CLLLC GaN Phase A (U8.12)
CLLLC_PRIM_FAULT_LEG2_H: PMP22650 Control (U31.4), PMP22650 CLLLC GaN Phase B (U14.12)
CLLLC_PRIM_FAULT_LEG2_L: PMP22650 Control (U31.5), PMP22650 CLLLC GaN Phase B (U12.12)
CLLLC_PRIM_LEG1_H: PMP22650 Control (J26.49), PMP22650 CLLLC GaN Phase A (R35.1)
CLLLC_PRIM_LEG1_H_TEMP: PMP22650 Control (U32.4), PMP22650 CLLLC GaN Phase A (U10.14)
CLLLC_PRIM_LEG1_L: PMP22650 Control (J26.51), PMP22650 CLLLC GaN Phase A (R30.1)
CLLLC_PRIM_LEG1_L_TEMP: PMP22650 Control (U33.4), PMP22650 CLLLC GaN Phase A (U8.14)
CLLLC_PRIM_LEG2_H: PMP22650 Control (J26.53), PMP22650 CLLLC GaN Phase B (R45.1)
CLLLC_PRIM_LEG2_H_TEMP: PMP22650 Control (U33.5), PMP22650 CLLLC GaN Phase B (U14.14)
CLLLC_PRIM_LEG2_L: PMP22650 Control (J26.55), PMP22650 CLLLC GaN Phase B (R40.1)
CLLLC_PRIM_LEG2_L_TEMP: PMP22650 Control (U32.5), PMP22650 CLLLC GaN Phase B (U12.14)
CLLLC_SEC_FAULT_LEG1_H: PMP22650 Control (U31.10), PMP22650 CLLLC GaN Phase C (U18.12)
CLLLC_SEC_FAULT_LEG1_L: PMP22650 Control (U31.9), PMP22650 CLLLC GaN Phase C (U16.12)
CLLLC_SEC_FAULT_LEG2_H: PMP22650 Control (U31.12), PMP22650 CLLLC GaN Phase D (U22.12)
CLLLC_SEC_FAULT_LEG2_L: PMP22650 Control (U31.13), PMP22650 CLLLC GaN Phase D (U20.12)
CLLLC_SEC_LEG1_H: PMP22650 Control (J26.50), PMP22650 CLLLC GaN Phase C (R55.1)
CLLLC_SEC_LEG1_H_TEMP: PMP22650 Control (U32.10), PMP22650 CLLLC GaN Phase C (U18.14)
CLLLC_SEC_LEG1_L: PMP22650 Control (J26.52), PMP22650 CLLLC GaN Phase C (R50.1)
CLLLC_SEC_LEG1_L_TEMP: PMP22650 Control (U33.10), PMP22650 CLLLC GaN Phase C (U16.14)
CLLLC_SEC_LEG2_H: PMP22650 Control (J26.54), PMP22650 CLLLC GaN Phase D (R65.1)
CLLLC_SEC_LEG2_H_TEMP: PMP22650 Control (U33.9), PMP22650 CLLLC GaN Phase D (U22.14)
CLLLC_SEC_LEG2_L: PMP22650 Control (J26.56), PMP22650 CLLLC GaN Phase D (R60.1)
CLLLC_SEC_LEG2_L_TEMP: PMP22650 Control (U32.9), PMP22650 CLLLC GaN Phase D (U20.14)
CLLLC_SEC_SIDE_SENSE_DIAG: PMP22650 Control (J26.80), PMP22650 CLLLC Secondary Sensing (J35.4)
CLLLC_VSEC: PMP22650 Control (J26.31), PMP22650 CLLLC Secondary Sensing (C241.1 R188.2)
ERRORSTS: PMP22650 Control (R84.2 R90.2), PMP22650 Bias Power and Monitors (R22.1 U1.2)
IPRI_SENSE: PMP22650 PFC Power Stage (14 pins), PMP22650 PFC GaN PH1 (41 pins), PMP22650 PFC GaN PH2 (41 pins), PMP22650 PFC LF FET Gate Driver (7 pins), PMP22650 CLLLC Primary Sensing (R82.1)
PFC_4H_G: PMP22650 PFC Power Stage (Q8.1 Q9.1), PMP22650 PFC LF FET Gate Driver (C197.1 R121.2 R122.2 R124.2)
PFC_4L_G: PMP22650 PFC Power Stage (Q6.1 Q7.1), PMP22650 PFC LF FET Gate Driver (C196.1 R117.2 R118.2 R119.2)
ROG_PRI_N: PMP22650 CLLLC Power Stage (T2.2), PMP22650 CLLLC Primary Sensing (R67.1)
ROG_PRI_P: PMP22650 CLLLC Power Stage (T2.1), PMP22650 CLLLC Primary Sensing (R69.1)
ROG_SEC_N: PMP22650 CLLLC Power Stage (J1.2), PMP22650 CLLLC Secondary Sensing (R179.1)
ROG_SEC_P: PMP22650 CLLLC Power Stage (J1.1), PMP22650 CLLLC Secondary Sensing (R181.1)
SW_A: PMP22650 CLLLC Power Stage (C10.2 C12.2 C14.2 C16.2), PMP22650 CLLLC GaN Phase A (49 pins)
SW_B: PMP22650 CLLLC Power Stage (C2.2 C4.2 C6.2 C8.2), PMP22650 CLLLC GaN Phase B (49 pins)
SW_C: PMP22650 CLLLC Power Stage (C11.2 C13.2 C15.2 C17.2), PMP22650 CLLLC GaN Phase C (49 pins)
SW_D: PMP22650 CLLLC Power Stage (C3.1 C5.1 C7.1 C9.1), PMP22650 CLLLC GaN Phase D (49 pins)
SYSTEM_DISABLE_FET_SUPPLY: PMP22650 Control (J26.85), PMP22650 Bias Power and Monitors (R18.2 U1.1)
SYSTEM_TEMP_1: PMP22650 Control (J26.27), PMP22650 CLLLC Primary Sensing (C135.1 R81.2)
SYSTEM_WATCHDOG_DISABLE: PMP22650 Control (J26.77), PMP22650 Bias Power and Monitors (R9.2)
SYSTEM_WATCHDOG_OUT: PMP22650 Control (J26.75), PMP22650 Bias Power and Monitors (U4.7)
TTPLPFC_GAN_FAULT_PH1_H: PMP22650 PFC GaN PH1 (U36.12), PMP22650 Control (U30.4)
TTPLPFC_GAN_FAULT_PH1_L: PMP22650 PFC GaN PH1 (U34.12), PMP22650 Control (U30.5)
TTPLPFC_GAN_FAULT_PH2_H: PMP22650 PFC GaN PH2 (U40.12), PMP22650 Control (U30.1)
TTPLPFC_GAN_FAULT_PH2_L: PMP22650 PFC GaN PH2 (U38.12), PMP22650 Control (U30.2)
TTPLPFC_GAN_OC_HIGH_FREQ_PH1_H: PMP22650 PFC GaN PH1 (U36.13), PMP22650 Control (R93.2)
TTPLPFC_GAN_OC_HIGH_FREQ_PH1_L: PMP22650 PFC GaN PH1 (U34.13), PMP22650 Control (R92.2)
TTPLPFC_GAN_OC_HIGH_FREQ_PH2_H: PMP22650 PFC GaN PH2 (U40.13), PMP22650 Control (J26.71)
TTPLPFC_GAN_OC_HIGH_FREQ_PH2_L: PMP22650 PFC GaN PH2 (U38.13), PMP22650 Control (J26.73)
TTPLPFC_HIGH_FREQ_PH1_H: PMP22650 PFC GaN PH1 (R106.1), PMP22650 Control (J26.61)
TTPLPFC_HIGH_FREQ_PH1_L: PMP22650 PFC GaN PH1 (R101.1), PMP22650 Control (J26.63)
TTPLPFC_HIGH_FREQ_PH2_H: PMP22650 PFC GaN PH2 (R116.1), PMP22650 Control (J26.58)
TTPLPFC_HIGH_FREQ_PH2_L: PMP22650 PFC GaN PH2 (R111.1), PMP22650 Control (J26.60)
TTPLPFC_IAC_PH1: PMP22650 PFC Power Stage (C209.1 R148.2), PMP22650 Control (J26.15)
TTPLPFC_IAC_PH2: PMP22650 PFC Power Stage (C203.1 R133.2), PMP22650 Control (J26.18)
TTPLPFC_INRUSH_RELAY: PMP22650 PFC Power Stage (C213.1 Q5.1 R156.2), PMP22650 Control (J26.64)
TTPLPFC_LOW_FREQ_H: PMP22650 PFC LF FET Gate Driver (R123.1), PMP22650 Control (J26.57)
TTPLPFC_LOW_FREQ_L: PMP22650 PFC LF FET Gate Driver (R120.1), PMP22650 Control (J26.59)
TTPLPFC_PH1_H_TEMP: PMP22650 PFC GaN PH1 (U36.14), PMP22650 Control (U32.2)
TTPLPFC_PH1_L_TEMP: PMP22650 PFC GaN PH2 (U40.14), PMP22650 Control (U33.2)
TTPLPFC_PH2_H_TEMP: PMP22650 PFC GaN PH2 (U38.14), PMP22650 Control (U33.3)
TTPLPFC_PH2_L_TEMP: PMP22650 PFC GaN PH1 (U34.14), PMP22650 Control (U32.3)
TTPLPFC_SW1: PMP22650 PFC Power Stage (L18.1), PMP22650 PFC GaN PH1 (49 pins)
TTPLPFC_SW2: PMP22650 PFC Power Stage (L18.4), PMP22650 PFC GaN PH2 (49 pins)
TTPLPFC_VAC: PMP22650 PFC Power Stage (C202.1 R130.2), PMP22650 Control (J26.39)
TTPLPFC_VAC_L: PMP22650 PFC Power Stage (C207.1 R141.1 R144.1), PMP22650 Control (J26.17)
TTPLPFC_VAC_N: PMP22650 PFC Power Stage (C210.1 R147.1 R152.1), PMP22650 Control (J26.14)
TTPLPFC_VBUS: PMP22650 Control (J26.20), PMP22650 CLLLC Primary Sensing (C132.1 R74.2)
XRSn: PMP22650 Control (R89.2 U51.11), PMP22650 Bias Power and Monitors (R19.2 R24.2 R204.2 U1.4)

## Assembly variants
001: not fitted C19 C21 C130 C131 C196 C197 C240 C241 C242 C243 C245 C246 C247 C248 C250 C256 C257 L19 Q1 Q2 R5 R16 R19 R24 R26 R31 R36 R41 R46 R51 R56 R61 R84 R89 R97 R102 R107 R112 R118 R122 R206 R208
